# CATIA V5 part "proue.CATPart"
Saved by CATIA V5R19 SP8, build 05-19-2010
Part number: Pièce5
Bounding box of the stored display mesh (mm): x -10 to 10, y -5 to 15, z -10 to 10
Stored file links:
  G:\IAO\IAO_2010\iao\IAO_MMS_Groupe3\PB\cgourmelen\Projet_IAO_gourmelen_camille\Projet_IAO_gourmelen_camille\proue.CATPart
  G:\IAO\IAO_2010\iao\IAO_MMS_Groupe3\PB\cgourmelen\Projet_IAO_gourmelen_camille\Projet_IAO_gourmelen_camille\Catia_Gourmelen\squelette total.CATProduct
  G:\IAO\IAO_2010\iao\IAO_MMS_Groupe3\PB\cgourmelen\Projet_IAO_gourmelen_camille\Projet_IAO_gourmelen_camille\Catia_Gourmelen\sproue.CATPart
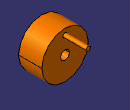
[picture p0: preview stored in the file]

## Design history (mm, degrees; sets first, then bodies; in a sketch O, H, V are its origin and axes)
Body1 (main body)
  Sketch1 on zx-plane, origin (0, 0, 0), H (-1, 0, 0), V (0, 0, 1)
    circle A1 centre (0, 0) radius 10
    circle A2 centre (0, 0) radius 2
    point P1 (0, 0)
    radius A1 = 10
    radius A2 = 2
    coincidence: P1 O
  Pad1: profile Sketch1, direction (0, 1, 0), length 5, mirrored extent
  Sketch2 on end face of Pad1, origin (0, 5, 0), H (-1, 0, 0), V (0, 0, 1)
    circle A1 centre (0, 7.268) radius 1
    point P1 (0, 7.268)
    radius A1 = 1
    distance P1 H = 7.268
    distance A1 V = 1
  Pad2: profile Sketch2, direction (0, 1, 0), length 10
